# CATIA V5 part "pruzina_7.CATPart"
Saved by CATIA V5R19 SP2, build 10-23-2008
Part number: Pruzina delka 16mm
Bounding box of the stored display mesh (mm): x -8 to 8, y -8 to 8, z 0 to 16
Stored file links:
  D:\DURATEC\pruzina_7.CATPart
  D:\DURATEC\pruzina_1.CATPart
  D:\DURATEC\Pohyb pruziny.CATProduct
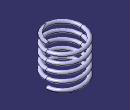
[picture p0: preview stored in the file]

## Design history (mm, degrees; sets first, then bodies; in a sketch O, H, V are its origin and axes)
External parameters (linked from other documents)
  `External.Delka pruziny` = 16 mm
  `External.Pocet zavitu` = 5
  `External.Vnitrni prumer pruziny` = 13 mm
  `External.Prumer dratu` = 1.5 mm
Set1
  Plane1: type Normal, Curve {line type PtDir, Direction (0, 0, 1), Start 0, End 16 {= `External.Delka pruziny`}, RefPoint {point type Coord, X 0, Y 0, Z 0}}, RefPoint vertex of Plane1
  Sketch1 on zx-plane, origin (0, 0, 0), H (-1, 0, 0), V (0, 0, 1)
    line L1 (6.5, 15) -> (6.5, 10)
    construction line L2 (6.5, 10) -> (-6.5, 10)
    line L3 (-6.5, 10) -> (-6.5, 15)
    construction line L4 (-6.5, 15) -> (6.5, 15)
    reference intersected line E1 through (0, 16) direction (-1, 0) from Plane1
    distance L3 L1 = 13 {= `External.Vnitrni prumer pruziny`}
    length L1 = 5
    distance L4 E1 = 1
    vertical: L1 V, L3 V
    horizontal: L2 H, L4 H
    equidistance: L1 L3 O
  Line1: type PtDir, Direction (0, 0, 1), Start 0, End 16 {= `External.Delka pruziny`}, RefPoint {point type Coord, X 0, Y 0, Z 0}
Body1 "Pruzina" (main body)
  Helix1: Pitch 3.2 {= `External.Delka pruziny` /`External.Pocet zavitu`}, TaperAngle 0, Height 16 {= Plane1.End}, Direction {line type PtDir, Direction (0, 0, 1), Start 0, End 16 {= `External.Delka pruziny`}, RefPoint {point type Coord, X 0, Y 0, Z 0}}, RefPoint {point type Coord, X 7.25 {= `External.Vnitrni prumer pruziny` /2+`External.Prumer dratu` /2}, Y 0, Z 0}
  Sketch2 on zx-plane, origin (0, 0, 0), H (-1, 0, 0), V (0, 0, 1)
    circle A1 centre (-7.25, 0) radius 0.75
    point P1 (-7.25, 0)
    reference projected point E1 (-7.25, 0) from vertex of Helix1
    radius A1 = 0.75 {= `External.Prumer dratu` /2}
    distance V A1 = 6.5 (reference)
    distance V A1 = 8 (reference)
    coincidence: P1 E1
  Rib1: profile Sketch2, centre curve Helix1
  Split1: SplitPlane xy-plane
  Split2: SplitPlane Plane1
